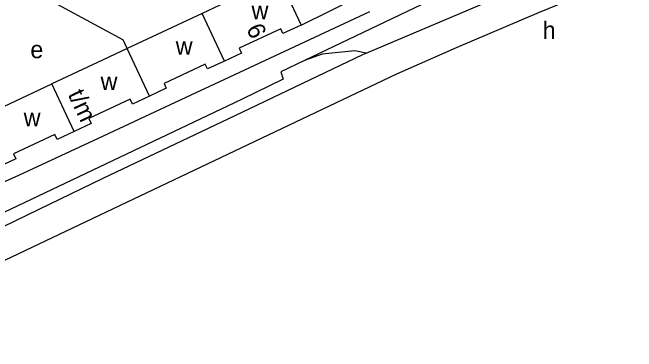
# Model space of a CAD drawing. Extents: x 158356 to 159894, y 383831 to 385260.
# Drawn here: x 159000.7 to 159143.9, y 383862.9 to 383940.7 of the extents above; entities that cross this region are included whole.
import ezdxf

# ---------------------------------------------------------------- set-up
doc = ezdxf.new("R2010")
doc.units = 0
for name, color, linetype in [('BLT_Basislijn', 7, 'Continuous'), ('BLT_Bebouwing', 7, 'Continuous'), ('BLT_Centroide', 7, 'Continuous'), ('BLT_Huisnummer_reeks', 7, 'Continuous'), ('BLT_Onderverdeling_panden', 7, 'Continuous')]:
    doc.layers.add(name, color=color, linetype=linetype)

msp = doc.modelspace()

# ---------------------------------------------------------------- linework, layer by layer
at = {"layer": 'BLT_Basislijn'}
for p, q in [((158999.29, 383949), (159026.07, 383934.41)), ((159045.95, 383923.82), (159082.7, 383940.91)), ((159027, 383932.43), (159026.07, 383934.41))]:
    msp.add_line(p, q, dxfattribs=at)
for points in [[(159183.57, 383991.39), (159156.91, 383975.82), (159119.63, 383954.56), (159067.69, 383929.66)], [(159088.93, 383926.66), (159102.6, 383932.65), (159121.62, 383940.74), (159139.46, 383948.12), (159156.35, 383954.78), (159168.72, 383959.06), (159184.17, 383964.54), (159200.11, 383969.53), (159206.72, 383971.51)], [(159081.85, 383931.35), (159109.84, 383943.2), (159117.99, 383946.75), (159125.88, 383953.07), (159144.67, 383960.83), (159152.29, 383961.04)], [(159066.93, 383937.81), (159080.25, 383944.43)], [(159051.79, 383917.05), (159081.11, 383931.03), (159081.85, 383931.35)], [(159081.85, 383931.35), (159079.25, 383931.89), (159071.79, 383931.15), (159067.69, 383929.66)], [(159067.69, 383929.66), (159062.28, 383927.05), (159062.84, 383925.37), (159053.28, 383920.71)], [(158949.95, 383862.91), (158960.72, 383867.95), (158971.31, 383872.04), (158981.41, 383875.89), (158992.71, 383880.94), (159088.93, 383926.66)], [(158973.85, 383891.02), (158986.52, 383896.41), (159002.13, 383903.34), (159020.44, 383911.89), (159042.83, 383922.34), (159045.95, 383923.82)], [(159053.28, 383920.71), (158992.49, 383891.93), (158991.27, 383893.7), (158983.13, 383889.76), (158981.5, 383888.54), (158980.42, 383886.91), (158980.28, 383885.96), (158980.96, 383885.42), (158982.35, 383885.39)], [(158982.35, 383885.39), (158993.58, 383889.36), (158998.46, 383891.53), (159004.3, 383894.38), (159021.53, 383902.66), (159051.79, 383917.05)]]:
    msp.add_lwpolyline(points, dxfattribs=at)
at = {"layer": 'BLT_Bebouwing'}
for p, q in [((159061.79, 383948.76), (159066.93, 383937.81)), ((159044.2, 383940.5), (159027, 383932.43)), ((159027, 383932.43), (159021.34, 383929.77)), ((159021.34, 383929.77), (159009.73, 383924.32))]:
    msp.add_line(p, q, dxfattribs=at)
for points in [[(159061.79, 383948.76), (159057.26, 383946.64), (159044.2, 383940.5)], [(159066.93, 383937.81), (159062.77, 383935.86), (159062.26, 383936.97), (159052.71, 383932.49), (159053.22, 383931.39), (159049.33, 383929.56)], [(159049.33, 383929.56), (159045.44, 383927.74), (159044.91, 383928.87), (159035.48, 383924.44), (159036, 383923.33), (159032.12, 383921.51)], [(158991.69, 383915.89), (159000, 383919.75), (159009.73, 383924.32)], [(159032.12, 383921.51), (159028.24, 383919.68), (159027.71, 383920.8), (159018.22, 383916.35), (159018.75, 383915.23), (159014.85, 383913.41)], [(159014.85, 383913.41), (159010.96, 383911.58), (159010.43, 383912.72), (159000.92, 383908.26), (159001.45, 383907.13), (159000, 383906.46), (158996.77, 383904.96)]]:
    msp.add_lwpolyline(points, dxfattribs=at)
at = {"layer": 'BLT_Onderverdeling_panden'}
for p, q in [((159049.33, 383929.56), (159044.2, 383940.5)), ((159032.12, 383921.51), (159027, 383932.43)), ((159014.85, 383913.41), (159009.73, 383924.32))]:
    msp.add_line(p, q, dxfattribs=at)

# ---------------------------------------------------------------- texts
at = {"layer": 'BLT_Centroide'}
for s, p in [('w', (159055.56, 383939.16)), ('h', (159122.35, 383934.63)), ('e', (159004.8, 383930.21)), ('w', (159038.16, 383931)), ('w', (159020.92, 383922.91)), ('w', (159003.27, 383914.62))]:
    msp.add_text(s, height=4, dxfattribs=at).set_placement(p)
at = {"layer": 'BLT_Huisnummer_reeks'}
for s, rotation, p in [('6', 295.1311, (159054.27, 383937.02)), ('t/m', 295.1346, (159013.33, 383921.94))]:
    msp.add_text(s, height=4, rotation=rotation, dxfattribs=at).set_placement(p)

doc.saveas('drawing.dxf')
